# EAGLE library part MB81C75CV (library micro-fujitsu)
MICROCONTROLLER/MEMORY DEVICE
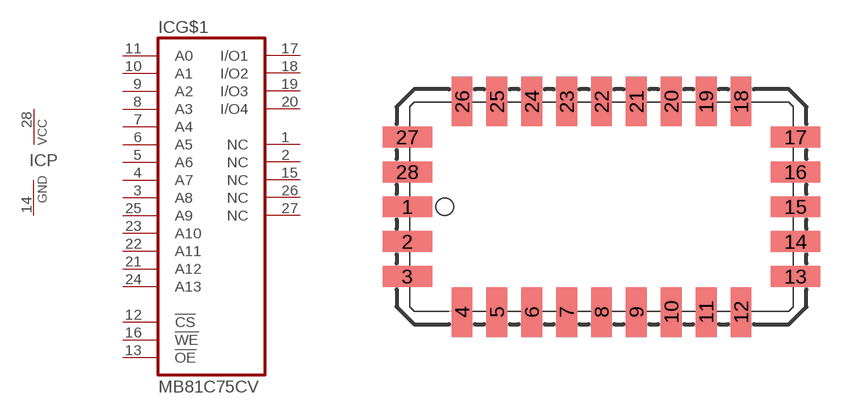
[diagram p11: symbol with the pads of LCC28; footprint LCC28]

Designator prefix IC; gates G$1=MB81C75C P=VCC-GND

## MB81C75CV (OC_FARNELL: unknown; OC_NEWARK: unknown)  [LCC28]
1  G$1:NC  nc
2  G$1:NC  nc
3  G$1:A8  in
4  G$1:A7  in
5  G$1:A6  in
6  G$1:A5  in
7  G$1:A4  in
8  G$1:A3  in
9  G$1:A2  in
10  G$1:A1  in
11  G$1:A0  in
12  G$1:!CS  in
13  G$1:!OE  in
14  P:GND  pwr
15  G$1:NC  nc
16  G$1:!WE  in
17  G$1:I/O1
18  G$1:I/O2
19  G$1:I/O3
20  G$1:I/O4  nc
21  G$1:A12  in
22  G$1:A11  in
23  G$1:A10  in
24  G$1:A13  in
25  G$1:A9  in
26  G$1:NC  nc
27  G$1:NC  nc
28  P:VCC  pwr

## Footprint LCC28 (pad centres in mm)
LEADED CHIP CARRIER rectangle
smd 1.8 x 0.76: 1 -7.07,0.635; 2 -7.07,-0.635; 3 -7.07,-1.905; 13 7.07,-1.905; 14 7.07,-0.635; 15 7.07,0.635; 16 7.07,1.905; 17 7.07,3.175; 27 -7.07,3.175; 28 -7.07,1.905
smd 0.76 x 1.8: 4 -5.08,-3.2; 5 -3.81,-3.2; 6 -2.54,-3.2; 7 -1.27,-3.2; 8 0,-3.2; 9 1.27,-3.2; 10 2.54,-3.2; 11 3.81,-3.2; 12 5.08,-3.2; 18 5.08,4.47; 19 3.81,4.47; 20 2.54,4.47; 21 1.27,4.47; 22 0,4.47; 23 -1.27,4.47; 24 -2.54,4.47; 25 -3.81,4.47; 26 -5.08,4.47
